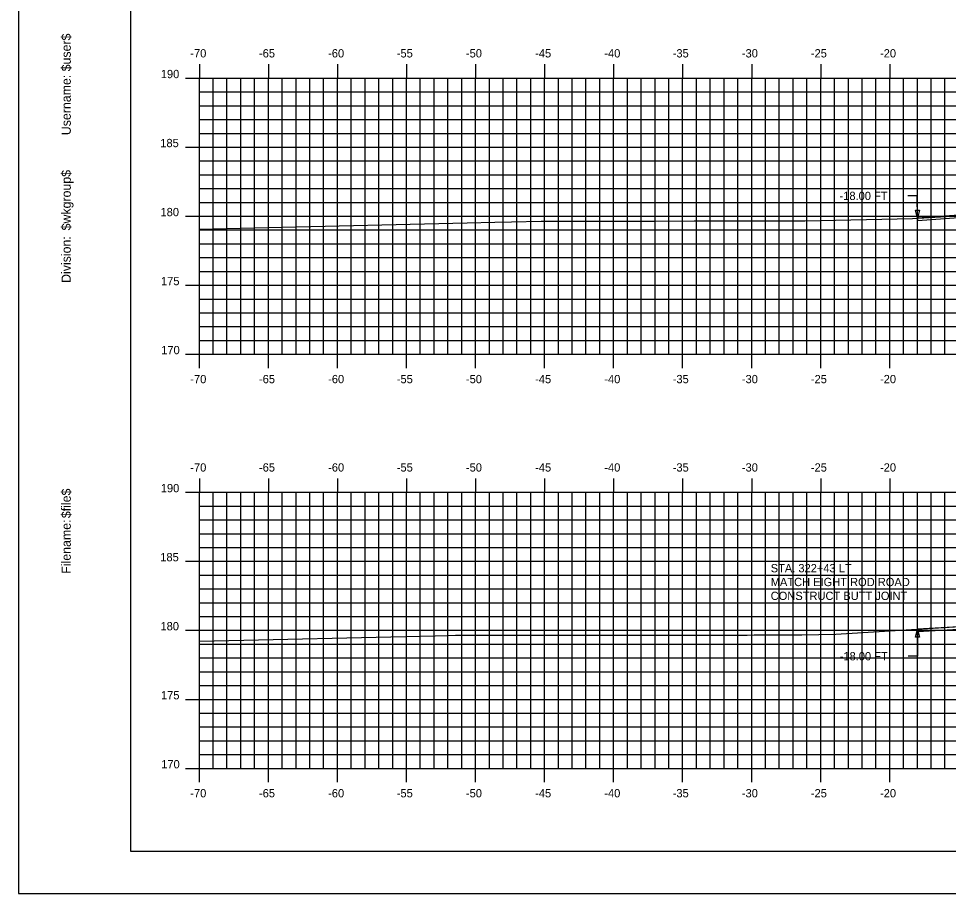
# Model space of a CAD drawing. Extents: x 1140094 to 1140264, y 608981 to 609091.
# Drawn here: x 1140093.6 to 1140161, y 608981.3 to 609044.6 of the extents above; entities that cross this region are included whole.
import ezdxf

# ---------------------------------------------------------------- set-up
doc = ezdxf.new("R2010")
doc.units = 0
for name, color, linetype in [('ANNOTATION', 7, 'Continuous'), ('BORDER', 7, 'Continuous'), ('D_Roadway_Edge_Shoulder', 7, 'Continuous'), ('D_Text_Standard', 7, 'Continuous'), ('H_V ANNOTATION', 7, 'Continuous'), ('MAJOR', 7, 'Continuous'), ('MINOR', 7, 'Continuous'), ('PLOT BOUNDARY', 7, 'Continuous'), ('S_Roadway_Centerline', 7, 'Continuous')]:
    doc.layers.add(name, color=color, linetype=linetype)

msp = doc.modelspace()

# ---------------------------------------------------------------- linework, layer by layer
at = {"layer": 'BORDER'}
msp.add_lwpolyline([(1140101.732, 608984.335), (1140261.732, 608984.335), (1140261.732, 609089.335), (1140101.732, 609089.335)], close=True, dxfattribs=at)
at = {"layer": 'D_Roadway_Edge_Shoulder'}
for points in [[(1140161.731, 609030.403), (1140158.731, 609030.183), (1140158.744, 609030.016), (1140161.73, 609030.236)], [(1140161.731, 609000.577), (1140158.731, 609000.415), (1140158.74, 609000.249), (1140161.731, 609000.41)]]:
    msp.add_lwpolyline(points, close=True, dxfattribs=at)
at = {"layer": 'D_Text_Standard'}
for points in [[(1140158.731, 609030.183), (1140158.726, 609031.806), (1140158.046, 609031.806)], [(1140158.731, 609000.415), (1140158.738, 608998.459), (1140158.058, 608998.459)]]:
    msp.add_lwpolyline(points, dxfattribs=at)
for points in [[(1140158.731, 609030.183), (1140158.584, 609030.764), (1140158.875, 609030.765)], [(1140158.731, 609000.415), (1140158.879, 608999.834), (1140158.588, 608999.833)]]:
    msp.add_lwpolyline(points, close=True, dxfattribs=at)
at = {"layer": 'MAJOR'}
for p, q in [((1140106.731, 609041.337), (1140106.731, 609040.335)), ((1140111.731, 609041.337), (1140111.731, 609040.335)), ((1140116.731, 609041.337), (1140116.731, 609040.335)), ((1140121.731, 609041.337), (1140121.731, 609040.335)), ((1140126.731, 609041.337), (1140126.731, 609040.335)), ((1140131.731, 609041.337), (1140131.731, 609040.335)), ((1140136.731, 609041.337), (1140136.731, 609040.335)), ((1140141.731, 609041.337), (1140141.731, 609040.335)), ((1140146.731, 609041.337), (1140146.731, 609040.335)), ((1140151.731, 609041.337), (1140151.731, 609040.335)), ((1140156.731, 609041.337), (1140156.731, 609040.335)), ((1140105.729, 609040.335), (1140106.731, 609040.335)), ((1140106.731, 609040.335), (1140246.731, 609040.335)), ((1140106.731, 609020.335), (1140106.731, 609040.335)), ((1140106.731, 609020.335), (1140106.731, 609040.335)), ((1140106.731, 609040.335), (1140246.731, 609040.335)), ((1140111.731, 609020.335), (1140111.731, 609040.335)), ((1140116.731, 609020.335), (1140116.731, 609040.335)), ((1140121.731, 609020.335), (1140121.731, 609040.335)), ((1140126.731, 609020.335), (1140126.731, 609040.335)), ((1140131.731, 609020.335), (1140131.731, 609040.335)), ((1140136.731, 609020.335), (1140136.731, 609040.335)), ((1140141.731, 609020.335), (1140141.731, 609040.335)), ((1140146.731, 609020.335), (1140146.731, 609040.335)), ((1140151.731, 609020.335), (1140151.731, 609040.335)), ((1140156.731, 609020.335), (1140156.731, 609040.335)), ((1140105.729, 609035.335), (1140106.731, 609035.335)), ((1140106.731, 609035.335), (1140246.731, 609035.335)), ((1140105.729, 609030.335), (1140106.731, 609030.335)), ((1140106.731, 609030.335), (1140246.731, 609030.335)), ((1140105.729, 609025.335), (1140106.731, 609025.335)), ((1140106.731, 609025.335), (1140246.731, 609025.335)), ((1140105.729, 609020.335), (1140106.731, 609020.335)), ((1140106.731, 609020.335), (1140246.731, 609020.335)), ((1140106.731, 609020.335), (1140246.731, 609020.335)), ((1140106.731, 609019.333), (1140106.731, 609020.335)), ((1140111.731, 609019.333), (1140111.731, 609020.335)), ((1140116.731, 609019.333), (1140116.731, 609020.335)), ((1140121.731, 609019.333), (1140121.731, 609020.335)), ((1140126.731, 609019.333), (1140126.731, 609020.335)), ((1140131.731, 609019.333), (1140131.731, 609020.335)), ((1140136.731, 609019.333), (1140136.731, 609020.335)), ((1140141.731, 609019.333), (1140141.731, 609020.335)), ((1140146.731, 609019.333), (1140146.731, 609020.335)), ((1140151.731, 609019.333), (1140151.731, 609020.335)), ((1140156.731, 609019.333), (1140156.731, 609020.335)), ((1140106.731, 609011.337), (1140106.731, 609010.335)), ((1140111.731, 609011.337), (1140111.731, 609010.335)), ((1140116.731, 609011.337), (1140116.731, 609010.335)), ((1140121.731, 609011.337), (1140121.731, 609010.335)), ((1140126.731, 609011.337), (1140126.731, 609010.335)), ((1140131.731, 609011.337), (1140131.731, 609010.335)), ((1140136.731, 609011.337), (1140136.731, 609010.335)), ((1140141.731, 609011.337), (1140141.731, 609010.335)), ((1140146.731, 609011.337), (1140146.731, 609010.335)), ((1140151.731, 609011.337), (1140151.731, 609010.335)), ((1140156.731, 609011.337), (1140156.731, 609010.335)), ((1140105.729, 609010.335), (1140106.731, 609010.335)), ((1140106.731, 609010.335), (1140246.731, 609010.335)), ((1140106.731, 608990.335), (1140106.731, 609010.335)), ((1140106.731, 608990.335), (1140106.731, 609010.335)), ((1140106.731, 609010.335), (1140246.731, 609010.335)), ((1140111.731, 608990.335), (1140111.731, 609010.335)), ((1140116.731, 608990.335), (1140116.731, 609010.335)), ((1140121.731, 608990.335), (1140121.731, 609010.335)), ((1140126.731, 608990.335), (1140126.731, 609010.335)), ((1140131.731, 608990.335), (1140131.731, 609010.335)), ((1140136.731, 608990.335), (1140136.731, 609010.335)), ((1140141.731, 608990.335), (1140141.731, 609010.335)), ((1140146.731, 608990.335), (1140146.731, 609010.335)), ((1140151.731, 608990.335), (1140151.731, 609010.335)), ((1140156.731, 608990.335), (1140156.731, 609010.335)), ((1140105.729, 609005.335), (1140106.731, 609005.335)), ((1140106.731, 609005.335), (1140246.731, 609005.335)), ((1140105.729, 609000.335), (1140106.731, 609000.335)), ((1140106.731, 609000.335), (1140246.731, 609000.335)), ((1140105.729, 608995.335), (1140106.731, 608995.335)), ((1140106.731, 608995.335), (1140246.731, 608995.335)), ((1140105.729, 608990.335), (1140106.731, 608990.335)), ((1140106.731, 608990.335), (1140246.731, 608990.335)), ((1140106.731, 608990.335), (1140246.731, 608990.335)), ((1140106.731, 608989.333), (1140106.731, 608990.335)), ((1140111.731, 608989.333), (1140111.731, 608990.335)), ((1140116.731, 608989.333), (1140116.731, 608990.335)), ((1140121.731, 608989.333), (1140121.731, 608990.335)), ((1140126.731, 608989.333), (1140126.731, 608990.335)), ((1140131.731, 608989.333), (1140131.731, 608990.335)), ((1140136.731, 608989.333), (1140136.731, 608990.335)), ((1140141.731, 608989.333), (1140141.731, 608990.335)), ((1140146.731, 608989.333), (1140146.731, 608990.335)), ((1140151.731, 608989.333), (1140151.731, 608990.335)), ((1140156.731, 608989.333), (1140156.731, 608990.335))]:
    msp.add_line(p, q, dxfattribs=at)
at = {"layer": 'MINOR'}
for p, q in [((1140107.731, 609020.335), (1140107.731, 609040.335)), ((1140108.731, 609020.335), (1140108.731, 609040.335)), ((1140109.731, 609020.335), (1140109.731, 609040.335)), ((1140110.731, 609020.335), (1140110.731, 609040.335)), ((1140112.731, 609020.335), (1140112.731, 609040.335)), ((1140113.731, 609020.335), (1140113.731, 609040.335)), ((1140114.731, 609020.335), (1140114.731, 609040.335)), ((1140115.731, 609020.335), (1140115.731, 609040.335)), ((1140117.731, 609020.335), (1140117.731, 609040.335)), ((1140118.731, 609020.335), (1140118.731, 609040.335)), ((1140119.731, 609020.335), (1140119.731, 609040.335)), ((1140120.731, 609020.335), (1140120.731, 609040.335)), ((1140122.731, 609020.335), (1140122.731, 609040.335)), ((1140123.731, 609020.335), (1140123.731, 609040.335)), ((1140124.731, 609020.335), (1140124.731, 609040.335)), ((1140125.731, 609020.335), (1140125.731, 609040.335)), ((1140127.731, 609020.335), (1140127.731, 609040.335)), ((1140128.731, 609020.335), (1140128.731, 609040.335)), ((1140129.731, 609020.335), (1140129.731, 609040.335)), ((1140130.731, 609020.335), (1140130.731, 609040.335)), ((1140132.731, 609020.335), (1140132.731, 609040.335)), ((1140133.731, 609020.335), (1140133.731, 609040.335)), ((1140134.731, 609020.335), (1140134.731, 609040.335)), ((1140135.731, 609020.335), (1140135.731, 609040.335)), ((1140137.731, 609020.335), (1140137.731, 609040.335)), ((1140138.731, 609020.335), (1140138.731, 609040.335)), ((1140139.731, 609020.335), (1140139.731, 609040.335)), ((1140140.731, 609020.335), (1140140.731, 609040.335)), ((1140142.731, 609020.335), (1140142.731, 609040.335)), ((1140143.731, 609020.335), (1140143.731, 609040.335)), ((1140144.731, 609020.335), (1140144.731, 609040.335)), ((1140145.731, 609020.335), (1140145.731, 609040.335)), ((1140147.731, 609020.335), (1140147.731, 609040.335)), ((1140148.731, 609020.335), (1140148.731, 609040.335)), ((1140149.731, 609020.335), (1140149.731, 609040.335)), ((1140150.731, 609020.335), (1140150.731, 609040.335)), ((1140152.731, 609020.335), (1140152.731, 609040.335)), ((1140153.731, 609020.335), (1140153.731, 609040.335)), ((1140154.731, 609020.335), (1140154.731, 609040.335)), ((1140155.731, 609020.335), (1140155.731, 609040.335)), ((1140157.731, 609020.335), (1140157.731, 609040.335)), ((1140158.731, 609020.335), (1140158.731, 609040.335)), ((1140159.731, 609020.335), (1140159.731, 609040.335)), ((1140160.731, 609020.335), (1140160.731, 609040.335)), ((1140106.731, 609039.335), (1140246.731, 609039.335)), ((1140106.731, 609039.335), (1140107.733, 609039.335)), ((1140106.731, 609038.335), (1140246.731, 609038.335)), ((1140106.731, 609038.335), (1140107.733, 609038.335)), ((1140106.731, 609037.335), (1140246.731, 609037.335)), ((1140106.731, 609037.335), (1140107.733, 609037.335)), ((1140106.731, 609036.335), (1140246.731, 609036.335)), ((1140106.731, 609036.335), (1140107.733, 609036.335)), ((1140106.731, 609034.335), (1140246.731, 609034.335)), ((1140106.731, 609034.335), (1140107.733, 609034.335)), ((1140106.731, 609033.335), (1140246.731, 609033.335)), ((1140106.731, 609033.335), (1140107.733, 609033.335)), ((1140106.731, 609032.335), (1140246.731, 609032.335)), ((1140106.731, 609032.335), (1140107.733, 609032.335)), ((1140106.731, 609031.335), (1140246.731, 609031.335)), ((1140106.731, 609031.335), (1140107.733, 609031.335)), ((1140106.731, 609029.335), (1140246.731, 609029.335)), ((1140106.731, 609029.335), (1140107.733, 609029.335)), ((1140106.731, 609028.335), (1140246.731, 609028.335)), ((1140106.731, 609028.335), (1140107.733, 609028.335)), ((1140106.731, 609027.335), (1140246.731, 609027.335)), ((1140106.731, 609027.335), (1140107.733, 609027.335)), ((1140106.731, 609026.335), (1140246.731, 609026.335)), ((1140106.731, 609026.335), (1140107.733, 609026.335)), ((1140106.731, 609024.335), (1140246.731, 609024.335)), ((1140106.731, 609024.335), (1140107.733, 609024.335)), ((1140106.731, 609023.335), (1140246.731, 609023.335)), ((1140106.731, 609023.335), (1140107.733, 609023.335)), ((1140106.731, 609022.335), (1140246.731, 609022.335)), ((1140106.731, 609022.335), (1140107.733, 609022.335)), ((1140106.731, 609021.335), (1140246.731, 609021.335)), ((1140106.731, 609021.335), (1140107.733, 609021.335)), ((1140107.731, 608990.335), (1140107.731, 609010.335)), ((1140108.731, 608990.335), (1140108.731, 609010.335)), ((1140109.731, 608990.335), (1140109.731, 609010.335)), ((1140110.731, 608990.335), (1140110.731, 609010.335)), ((1140112.731, 608990.335), (1140112.731, 609010.335)), ((1140113.731, 608990.335), (1140113.731, 609010.335)), ((1140114.731, 608990.335), (1140114.731, 609010.335)), ((1140115.731, 608990.335), (1140115.731, 609010.335)), ((1140117.731, 608990.335), (1140117.731, 609010.335)), ((1140118.731, 608990.335), (1140118.731, 609010.335)), ((1140119.731, 608990.335), (1140119.731, 609010.335)), ((1140120.731, 608990.335), (1140120.731, 609010.335)), ((1140122.731, 608990.335), (1140122.731, 609010.335)), ((1140123.731, 608990.335), (1140123.731, 609010.335)), ((1140124.731, 608990.335), (1140124.731, 609010.335)), ((1140125.731, 608990.335), (1140125.731, 609010.335)), ((1140127.731, 608990.335), (1140127.731, 609010.335)), ((1140128.731, 608990.335), (1140128.731, 609010.335)), ((1140129.731, 608990.335), (1140129.731, 609010.335)), ((1140130.731, 608990.335), (1140130.731, 609010.335)), ((1140132.731, 608990.335), (1140132.731, 609010.335)), ((1140133.731, 608990.335), (1140133.731, 609010.335)), ((1140134.731, 608990.335), (1140134.731, 609010.335)), ((1140135.731, 608990.335), (1140135.731, 609010.335)), ((1140137.731, 608990.335), (1140137.731, 609010.335)), ((1140138.731, 608990.335), (1140138.731, 609010.335)), ((1140139.731, 608990.335), (1140139.731, 609010.335)), ((1140140.731, 608990.335), (1140140.731, 609010.335)), ((1140142.731, 608990.335), (1140142.731, 609010.335)), ((1140143.731, 608990.335), (1140143.731, 609010.335)), ((1140144.731, 608990.335), (1140144.731, 609010.335)), ((1140145.731, 608990.335), (1140145.731, 609010.335)), ((1140147.731, 608990.335), (1140147.731, 609010.335)), ((1140148.731, 608990.335), (1140148.731, 609010.335)), ((1140149.731, 608990.335), (1140149.731, 609010.335)), ((1140150.731, 608990.335), (1140150.731, 609010.335)), ((1140152.731, 608990.335), (1140152.731, 609010.335)), ((1140153.731, 608990.335), (1140153.731, 609010.335)), ((1140154.731, 608990.335), (1140154.731, 609010.335)), ((1140155.731, 608990.335), (1140155.731, 609010.335)), ((1140157.731, 608990.335), (1140157.731, 609010.335)), ((1140158.731, 608990.335), (1140158.731, 609010.335)), ((1140159.731, 608990.335), (1140159.731, 609010.335)), ((1140160.731, 608990.335), (1140160.731, 609010.335)), ((1140106.731, 609009.335), (1140246.731, 609009.335)), ((1140106.731, 609009.335), (1140107.733, 609009.335)), ((1140106.731, 609008.335), (1140246.731, 609008.335)), ((1140106.731, 609008.335), (1140107.733, 609008.335)), ((1140106.731, 609007.335), (1140246.731, 609007.335)), ((1140106.731, 609007.335), (1140107.733, 609007.335)), ((1140106.731, 609006.335), (1140246.731, 609006.335)), ((1140106.731, 609006.335), (1140107.733, 609006.335)), ((1140106.731, 609004.335), (1140246.731, 609004.335)), ((1140106.731, 609004.335), (1140107.733, 609004.335)), ((1140106.731, 609003.335), (1140246.731, 609003.335)), ((1140106.731, 609003.335), (1140107.733, 609003.335)), ((1140106.731, 609002.335), (1140246.731, 609002.335)), ((1140106.731, 609002.335), (1140107.733, 609002.335)), ((1140106.731, 609001.335), (1140246.731, 609001.335)), ((1140106.731, 609001.335), (1140107.733, 609001.335)), ((1140106.731, 608999.335), (1140246.731, 608999.335)), ((1140106.731, 608999.335), (1140107.733, 608999.335)), ((1140106.731, 608998.335), (1140246.731, 608998.335)), ((1140106.731, 608998.335), (1140107.733, 608998.335)), ((1140106.731, 608997.335), (1140246.731, 608997.335)), ((1140106.731, 608997.335), (1140107.733, 608997.335)), ((1140106.731, 608996.335), (1140246.731, 608996.335)), ((1140106.731, 608996.335), (1140107.733, 608996.335)), ((1140106.731, 608994.335), (1140246.731, 608994.335)), ((1140106.731, 608994.335), (1140107.733, 608994.335)), ((1140106.731, 608993.335), (1140246.731, 608993.335)), ((1140106.731, 608993.335), (1140107.733, 608993.335)), ((1140106.731, 608992.335), (1140246.731, 608992.335)), ((1140106.731, 608992.335), (1140107.733, 608992.335)), ((1140106.731, 608991.335), (1140246.731, 608991.335)), ((1140106.731, 608991.335), (1140107.733, 608991.335))]:
    msp.add_line(p, q, dxfattribs=at)
at = {"layer": 'PLOT BOUNDARY'}
msp.add_lwpolyline([(1140093.638, 608981.276), (1140263.638, 608981.276), (1140263.638, 609091.276), (1140093.638, 609091.276)], close=True, dxfattribs=at)
at = {"layer": 'S_Roadway_Centerline'}
for points in [[(1140106.731, 609029.395), (1140111.717, 609029.523), (1140126.126, 609029.861), (1140128.129, 609029.906), (1140129.347, 609029.931), (1140131.475, 609029.969), (1140138.239, 609029.971), (1140139.776, 609029.984), (1140142.576, 609030.002), (1140144.991, 609030.01), (1140146.391, 609030.01), (1140148.725, 609030.005), (1140150.588, 609029.993), (1140158.37, 609030.161), (1140166.477, 609030.655)], [(1140106.731, 608999.54), (1140123.819, 608999.94), (1140124.73, 608999.961), (1140125.284, 608999.972), (1140126.251, 608999.99), (1140146.414, 608999.995), (1140146.904, 608999.999), (1140147.798, 609000.005), (1140148.569, 609000.008), (1140149.015, 609000.008), (1140149.76, 609000.006), (1140150.355, 609000.002), (1140152.837, 609000.056), (1140166.518, 609000.891)]]:
    msp.add_lwpolyline(points, dxfattribs=at)

# ---------------------------------------------------------------- texts
at = {"layer": 'ANNOTATION'}
for s, p in [('STA. 322+43 LT', (1140148.108, 609004.537)), ('MATCH EIGHT ROD ROAD', (1140148.108, 609003.535)), ('CONSTRUCT BUTT JOINT', (1140148.108, 609002.533))]:
    msp.add_text(s, height=0.6, dxfattribs=at).set_placement(p)
at = {"layer": 'BORDER'}
for s, p in [('$user$', (1140097.417, 609040.827)), ('Username:', (1140097.417, 609036.203)), ('$wkgroup$', (1140097.417, 609029.305)), ('Division:', (1140097.417, 609025.501)), ('$file$', (1140097.417, 609008.461)), ('Filename:', (1140097.417, 609004.433))]:
    msp.add_text(s, height=0.6696, rotation=90, dxfattribs=at).set_placement(p)
at = {"layer": 'D_Text_Standard'}
for p in [(1140153.094, 609031.506), (1140153.106, 608998.159)]:
    msp.add_text('-18.00 FT', height=0.6, dxfattribs=at).set_placement(p)
at = {"layer": 'H_V ANNOTATION'}
for s, p in [('-70', (1140106.073, 609041.835)), ('-65', (1140111.049, 609041.835)), ('-60', (1140116.057, 609041.835)), ('-50', (1140126.036, 609041.835)), ('-40', (1140136.057, 609041.835)), ('-35', (1140141.012, 609041.835)), ('-30', (1140146.02, 609041.835)), ('-25', (1140151.017, 609041.835)), ('-20', (1140156.025, 609041.835)), ('-55', (1140121.028, 609041.835)), ('-45', (1140131.049, 609041.835)), ('190', (1140103.936, 609040.335)), ('185', (1140103.899, 609035.335)), ('180', (1140103.915, 609030.335)), ('175', (1140103.952, 609025.335)), ('170', (1140103.968, 609020.335)), ('-70', (1140106.073, 609018.235)), ('-65', (1140111.049, 609018.235)), ('-60', (1140116.057, 609018.235)), ('-55', (1140121.028, 609018.235)), ('-50', (1140126.036, 609018.235)), ('-45', (1140131.049, 609018.235)), ('-40', (1140136.057, 609018.235)), ('-35', (1140141.012, 609018.235)), ('-30', (1140146.02, 609018.235)), ('-25', (1140151.017, 609018.235)), ('-20', (1140156.025, 609018.235)), ('-70', (1140106.073, 609011.835)), ('-65', (1140111.049, 609011.835)), ('-60', (1140116.057, 609011.835)), ('-55', (1140121.028, 609011.835)), ('-50', (1140126.036, 609011.835)), ('-45', (1140131.049, 609011.835)), ('-40', (1140136.057, 609011.835)), ('-35', (1140141.012, 609011.835)), ('-30', (1140146.02, 609011.835)), ('-25', (1140151.017, 609011.835)), ('-20', (1140156.025, 609011.835)), ('190', (1140103.936, 609010.335)), ('185', (1140103.899, 609005.335)), ('180', (1140103.915, 609000.335)), ('175', (1140103.952, 608995.335)), ('170', (1140103.968, 608990.335)), ('-70', (1140106.073, 608988.235)), ('-65', (1140111.049, 608988.235)), ('-60', (1140116.057, 608988.235)), ('-55', (1140121.028, 608988.235)), ('-50', (1140126.036, 608988.235)), ('-45', (1140131.049, 608988.235)), ('-40', (1140136.057, 608988.235)), ('-35', (1140141.012, 608988.235)), ('-30', (1140146.02, 608988.235)), ('-25', (1140151.017, 608988.235)), ('-20', (1140156.025, 608988.235))]:
    msp.add_text(s, height=0.6, dxfattribs=at).set_placement(p)
at = {"layer": 'MAJOR'}
for p in [(1140106.727, 609020.335), (1140106.727, 608990.335)]:
    msp.add_text('-', height=0.006, dxfattribs=at).set_placement(p)

doc.saveas('drawing.dxf')
